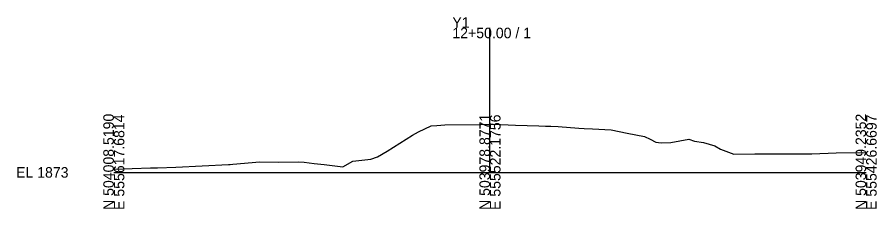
# Model space of a CAD drawing. Extents: x -26 to 203, y -10 to 5015.
# Drawn here: x -25.7 to 202.8, y 2490.3 to 2541.3 of the extents above; entities that cross this region are included whole.
import ezdxf

# ---------------------------------------------------------------- set-up
doc = ezdxf.new("R2010")
doc.units = 0
doc.layers.add('Exist Cross Section Cell', color=7, linetype='Continuous')
doc.layers.add('Exist XS Ground Line', color=7, linetype='Continuous')

msp = doc.modelspace()

# ---------------------------------------------------------------- linework, layer by layer
at = {"layer": 'Exist Cross Section Cell'}
for p, q in [((100, 2500), (100, 2538.49)), ((0, 2500), (100, 2500)), ((100, 2500), (200, 2500))]:
    msp.add_line(p, q, dxfattribs=at)
at = {"layer": 'Exist XS Ground Line'}
for p, q in [((81, 2510.81), (84.39, 2512.37)), ((84.39, 2512.37), (85.85, 2512.46)), ((85.85, 2512.46), (87.97, 2512.62)), ((87.97, 2512.62), (97.55, 2512.78)), ((97.55, 2512.78), (100, 2512.82)), ((100, 2512.82), (100.83, 2512.83)), ((100.83, 2512.83), (106.78, 2512.58)), ((106.78, 2512.58), (112.95, 2512.39)), ((112.95, 2512.39), (114.76, 2512.34)), ((114.76, 2512.34), (116.18, 2512.29)), ((116.18, 2512.29), (118.11, 2512.19)), ((118.11, 2512.19), (123.64, 2511.79)), ((123.64, 2511.79), (125.03, 2511.7)), ((125.03, 2511.7), (127.27, 2511.62)), ((127.27, 2511.62), (132.21, 2511.36)), ((72.67, 2505.66), (79.36, 2509.9)), ((79.36, 2509.9), (81, 2510.81)), ((132.21, 2511.36), (136.44, 2510.42)), ((136.44, 2510.42), (141.11, 2509.57)), ((141.11, 2509.57), (142.61, 2508.81)), ((142.61, 2508.81), (144.12, 2508.03)), ((144.12, 2508.03), (145.52, 2507.85)), ((145.52, 2507.85), (148.05, 2507.92)), ((148.05, 2507.92), (152.86, 2508.88)), ((152.86, 2508.88), (154.37, 2508.33)), ((154.37, 2508.33), (156.76, 2507.97)), ((156.76, 2507.97), (159.78, 2507.08)), ((159.78, 2507.08), (161.31, 2506.15)), ((70.06, 2504.16), (72.67, 2505.66)), ((161.31, 2506.15), (164.85, 2504.84)), ((164.85, 2504.84), (170.37, 2504.97)), ((170.37, 2504.97), (177.68, 2504.91)), ((177.68, 2504.91), (185.59, 2504.93)), ((185.59, 2504.93), (192.01, 2505.2)), ((192.01, 2505.2), (200, 2505.3)), ((31.66, 2502.2), (38.84, 2502.8)), ((38.84, 2502.8), (43.8, 2502.75)), ((43.8, 2502.75), (49.07, 2502.79)), ((49.07, 2502.79), (50.62, 2502.7)), ((50.62, 2502.7), (53.26, 2502.36)), ((60.88, 2501.52), (63.5, 2502.98)), ((63.5, 2502.98), (68.3, 2503.48)), ((68.3, 2503.48), (70.06, 2504.16)), ((0, 2500.84), (9.73, 2501.21)), ((9.73, 2501.21), (11.6, 2501.2)), ((11.6, 2501.2), (16.5, 2501.35)), ((16.5, 2501.35), (30.47, 2502.1)), ((30.47, 2502.1), (30.95, 2502.14)), ((30.95, 2502.14), (31.66, 2502.2)), ((53.26, 2502.36), (55.94, 2502.12)), ((55.94, 2502.12), (60.88, 2501.52))]:
    msp.add_line(p, q, dxfattribs=at)

# ---------------------------------------------------------------- texts
at = {"layer": 'Exist Cross Section Cell'}
for s, p in [('Y1', (90, 2538.49)), ('12+50.00 / 1', (90, 2535.69)), ('EL 1873', (-26, 2498.6))]:
    msp.add_text(s, height=2.8, dxfattribs=at).set_placement(p)
for s, p in [('N 504008.5190', (0, 2490)), ('E 555617.6814', (2.8, 2490)), ('N 503978.8771', (100, 2490)), ('E 555522.1756', (102.8, 2490)), ('N 503949.2352', (200, 2490)), ('E 555426.6697', (202.8, 2490))]:
    msp.add_text(s, height=2.8, rotation=90, dxfattribs=at).set_placement(p)

doc.saveas('drawing.dxf')
